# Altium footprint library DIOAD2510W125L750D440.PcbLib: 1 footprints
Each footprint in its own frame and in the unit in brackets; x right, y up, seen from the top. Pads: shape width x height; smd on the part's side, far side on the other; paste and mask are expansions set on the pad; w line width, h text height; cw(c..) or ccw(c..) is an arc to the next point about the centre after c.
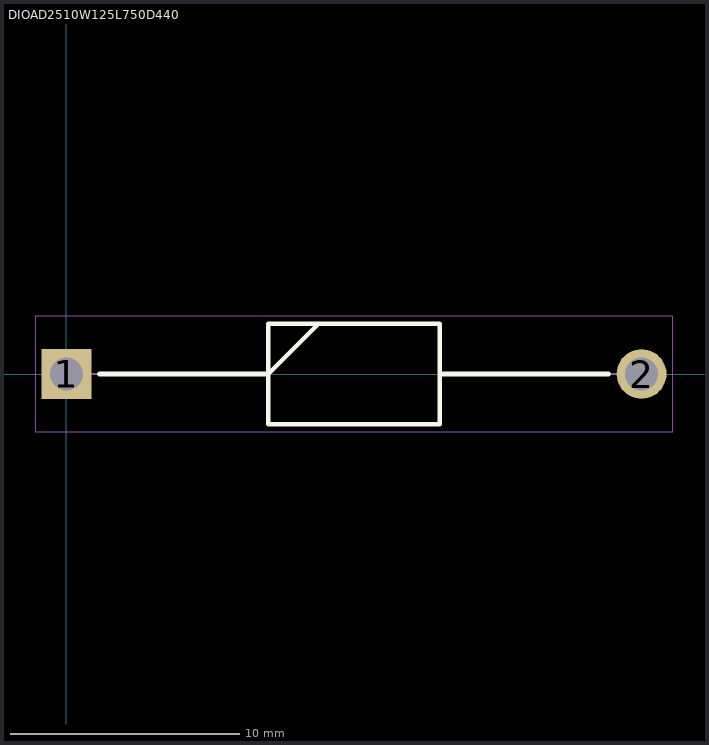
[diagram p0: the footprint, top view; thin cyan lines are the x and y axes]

## DIOAD2510W125L750D440 [mm]
pads (2):
  rect 2.175x2.175 / inner round 2.175 / far side rect 2.175x2.175 hole 1.45: 1(0,0)
  round 2.175 hole 1.45: 2(25.1,0)
Top Overlay:
  lines w0.2: 1.438,0 8.8,0 11,2.2 ; 16.3,0 23.662,0 ; 8.8,-2.2 16.3,-2.2 16.3,2.2 8.8,2.2 8.8,-2.2
Mechanical 15:
  lines w0.1: 0,0 8.8,0 11,2.2 ; 16.3,0 25.1,0 ; 8.8,-2.2 16.3,-2.2 16.3,2.2 8.8,2.2 8.8,-2.2
Mechanical 20:
  lines w0.05: -1.338,-2.55 26.437,-2.55 26.437,2.55 -1.338,2.55 -1.338,-2.55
